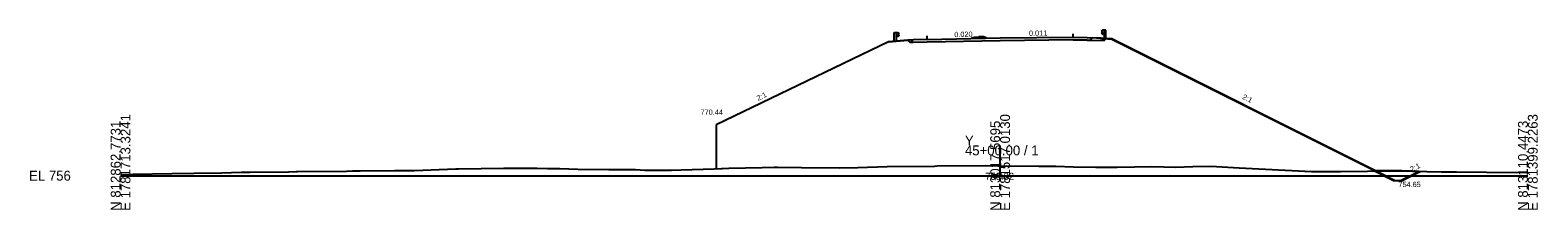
# Model space of a CAD drawing. Extents: x -12583 to 5303, y -44 to 25667.
# Drawn here: x 2874.3 to 3302.8, y 5490.3 to 5541.3 of the extents above; entities that cross this region are included whole.
import ezdxf

# ---------------------------------------------------------------- set-up
doc = ezdxf.new("R2010")
doc.units = 0
for name, color, linetype in [('Exist Cross Section Cell', 7, 'Continuous'), ('Exist XS Center Line Elevation Label', 7, 'Continuous'), ('Exist XS Ground Line', 7, 'Continuous'), ('Prop Conc 5in Monolithic Surface Mount Island', 7, 'Continuous'), ('Prop XS Ditch Standard Text', 7, 'Continuous'), ('Prop XS Dump Level', 7, 'Continuous'), ('Prop XS Earthwork Shape', 7, 'Continuous'), ('Prop XS EOT Tick Mark', 7, 'Continuous'), ('Prop XS Finish Grade', 7, 'Continuous'), ('Prop XS Finish Grade Earthwork', 7, 'Continuous'), ('Prop XS Finish Grade Paved Shoulder', 7, 'Continuous'), ('Prop XS Finish Grade Pavement', 7, 'Continuous'), ('Prop XS Guardrail', 7, 'Continuous'), ('Prop XS Pvmt Edge Slope', 7, 'Continuous'), ('Prop XS SE Text', 7, 'Continuous'), ('Prop XS Side Slope Text', 7, 'Continuous'), ('Prop XS Subgrade Earthwork', 7, 'Continuous')]:
    doc.layers.add(name, color=color, linetype=linetype)

msp = doc.modelspace()

# ---------------------------------------------------------------- linework, layer by layer
at = {"layer": 'Exist Cross Section Cell'}
for p, q in [((3150, 5500), (3150, 5508.57)), ((2900, 5500), (3150, 5500)), ((3150, 5500), (3300, 5500))]:
    msp.add_line(p, q, dxfattribs=at)
at = {"layer": 'Exist XS Ground Line'}
for p, q in [((3072.91, 5502.09), (3082.41, 5502.36)), ((3082.41, 5502.36), (3085.81, 5502.41)), ((3085.81, 5502.41), (3086.7, 5502.42)), ((3086.7, 5502.42), (3093.52, 5502.34)), ((3109.6, 5502.3), (3117.91, 5502.61)), ((3117.91, 5502.61), (3131.31, 5502.73)), ((3131.31, 5502.73), (3132.13, 5502.76)), ((3132.13, 5502.76), (3145.93, 5502.86)), ((3145.93, 5502.86), (3149.35, 5502.83)), ((3149.35, 5502.83), (3150, 5502.82)), ((3150, 5502.82), (3161.05, 5502.71)), ((3161.05, 5502.71), (3165.82, 5502.67)), ((3165.82, 5502.67), (3170.83, 5502.48)), ((3170.83, 5502.48), (3177.24, 5502.39)), ((3177.24, 5502.39), (3183.26, 5502.37)), ((3183.26, 5502.37), (3193.16, 5502.6)), ((3193.16, 5502.6), (3199.99, 5502.41)), ((3199.99, 5502.41), (3204.77, 5502.63)), ((3204.77, 5502.63), (3209.89, 5502.73)), ((3209.89, 5502.73), (3217.99, 5502.25)), ((2900, 5500.38), (2903.49, 5500.41)), ((2903.49, 5500.41), (2914.56, 5500.59)), ((2914.56, 5500.59), (2920.88, 5500.7)), ((2920.88, 5500.7), (2928.76, 5500.83)), ((2928.76, 5500.83), (2934.26, 5500.97)), ((2934.26, 5500.97), (2936.86, 5501.01)), ((2936.86, 5501.01), (2947.74, 5501.13)), ((2947.74, 5501.13), (2949.9, 5501.14)), ((2949.9, 5501.14), (2950.3, 5501.14)), ((2950.3, 5501.14), (2964.19, 5501.3)), ((2964.19, 5501.3), (2965.9, 5501.33)), ((2965.9, 5501.33), (2968.08, 5501.36)), ((2968.08, 5501.36), (2977.84, 5501.51)), ((2977.84, 5501.51), (2983.51, 5501.51)), ((2983.51, 5501.51), (2995.34, 5501.93)), ((2995.34, 5501.93), (2996.06, 5501.94)), ((2996.06, 5501.94), (3008.9, 5502.17)), ((3008.9, 5502.17), (3018.45, 5502.09)), ((3018.45, 5502.09), (3021.36, 5502.06)), ((3021.36, 5502.06), (3024.82, 5502)), ((3024.82, 5502), (3030.01, 5501.84)), ((3030.01, 5501.84), (3038.78, 5501.73)), ((3038.78, 5501.73), (3046.36, 5501.71)), ((3046.36, 5501.71), (3049.04, 5501.59)), ((3049.04, 5501.59), (3052.99, 5501.53)), ((3052.99, 5501.53), (3055.39, 5501.54)), ((3055.39, 5501.54), (3056.64, 5501.53)), ((3056.64, 5501.53), (3059.38, 5501.62)), ((3059.38, 5501.62), (3068.7, 5501.92)), ((3068.7, 5501.92), (3072.91, 5502.09)), ((3093.52, 5502.34), (3104.39, 5502.26)), ((3104.39, 5502.26), (3109.6, 5502.3)), ((3217.99, 5502.25), (3238.49, 5501.23)), ((3238.49, 5501.23), (3246.77, 5501.14)), ((3246.77, 5501.14), (3254.38, 5501.31)), ((3254.38, 5501.31), (3264.19, 5501.39)), ((3264.19, 5501.39), (3267.22, 5501.28)), ((3267.22, 5501.28), (3275.36, 5501.06)), ((3275.36, 5501.06), (3279.73, 5501.05)), ((3279.73, 5501.05), (3296.73, 5500.88)), ((3296.73, 5500.88), (3300, 5501))]:
    msp.add_line(p, q, dxfattribs=at)
at = {"layer": 'Prop Conc 5in Monolithic Surface Mount Island'}
for p, q in [((3142, 5539.1), (3142.74, 5539.36)), ((3142, 5538.93), (3142, 5539.1)), ((3142.74, 5539.36), (3143.99, 5539.41)), ((3145.24, 5539.41), (3143.99, 5539.41)), ((3146, 5539.18), (3145.24, 5539.41)), ((3146, 5539.01), (3146, 5539.18))]:
    msp.add_line(p, q, dxfattribs=at)
at = {"layer": 'Prop XS Dump Level'}
for p, q in [((3129.25, 5538.67), (3150, 5539.09)), ((3150, 5539.09), (3170.75, 5539.31))]:
    msp.add_line(p, q, dxfattribs=at)
at = {"layer": 'Prop XS Earthwork Shape'}
for points in [[(3069.3, 5514.44), (3069.3, 5501.94), (3072.91, 5502.09), (3082.41, 5502.36), (3085.81, 5502.41), (3086.7, 5502.42), (3093.52, 5502.34), (3104.39, 5502.26), (3109.6, 5502.3), (3117.91, 5502.61), (3131.31, 5502.73), (3132.13, 5502.76), (3145.93, 5502.86), (3149.35, 5502.83), (3150, 5502.82), (3161.05, 5502.71), (3165.82, 5502.67), (3170.83, 5502.48), (3177.24, 5502.39), (3183.26, 5502.37), (3193.16, 5502.6), (3199.99, 5502.41), (3204.77, 5502.63), (3209.89, 5502.73), (3217.99, 5502.25), (3238.49, 5501.23), (3246.77, 5501.14), (3254.38, 5501.31), (3256.44, 5501.33), (3181.75, 5538.67), (3176.25, 5539.11), (3175.56, 5538.42), (3174.75, 5538.44), (3170.75, 5538.52), (3150, 5538.3), (3129.25, 5537.88), (3125.25, 5537.8), (3124.44, 5537.79), (3123.75, 5538.47), (3118.25, 5538.03)], [(3263.8, 5498.65), (3268.97, 5501.23), (3267.22, 5501.28), (3264.19, 5501.39), (3256.44, 5501.33), (3261.8, 5498.65)]]:
    msp.add_lwpolyline(points, close=True, dxfattribs=at)
at = {"layer": 'Prop XS EOT Tick Mark'}
for p, q in [((3129.25, 5538.67), (3129.25, 5539.67)), ((3170.75, 5539.31), (3170.75, 5540.31))]:
    msp.add_line(p, q, dxfattribs=at)
at = {"layer": 'Prop XS Finish Grade'}
for p, q in [((3125.25, 5538.59), (3123.75, 5538.47)), ((3178.75, 5539.15), (3180.25, 5539.03))]:
    msp.add_line(p, q, dxfattribs=at)
at = {"layer": 'Prop XS Finish Grade Earthwork'}
for p, q in [((3118.25, 5538.03), (3069.3, 5514.44)), ((3118.25, 5538.03), (3123.75, 5538.47)), ((3180.25, 5539.03), (3181.75, 5538.91)), ((3181.75, 5538.91), (3256.91, 5501.33)), ((3069.3, 5514.44), (3069.3, 5501.94)), ((3256.91, 5501.33), (3262.28, 5498.65)), ((3262.28, 5498.65), (3264.28, 5498.65)), ((3264.28, 5498.65), (3269.43, 5501.22))]:
    msp.add_line(p, q, dxfattribs=at)
at = {"layer": 'Prop XS Finish Grade Paved Shoulder'}
for p, q in [((3129.25, 5538.67), (3125.25, 5538.59)), ((3170.75, 5539.31), (3178.75, 5539.15))]:
    msp.add_line(p, q, dxfattribs=at)
at = {"layer": 'Prop XS Finish Grade Pavement'}
for p, q in [((3129.25, 5538.67), (3150, 5539.09)), ((3150, 5539.09), (3170.75, 5539.31)), ((3150, 5539.09), (3170.75, 5539.31))]:
    msp.add_line(p, q, dxfattribs=at)
at = {"layer": 'Prop XS Guardrail'}
for p, q in [((3178.78, 5541.11), (3178.75, 5541.05)), ((3178.75, 5541.05), (3178.78, 5540.99)), ((3179.07, 5541.31), (3178.78, 5541.11)), ((3178.78, 5540.99), (3179.07, 5540.79)), ((3179.57, 5541.31), (3179.07, 5541.31)), ((3180.07, 5541.31), (3179.57, 5541.31)), ((3179.57, 5541.31), (3179.57, 5538.81)), ((3180.07, 5538.81), (3180.07, 5541.31)), ((3119.93, 5540.67), (3120.43, 5540.67)), ((3119.93, 5538.17), (3119.93, 5540.67)), ((3120.43, 5540.67), (3120.93, 5540.67)), ((3120.43, 5540.67), (3120.43, 5538.17)), ((3120.93, 5539.54), (3120.43, 5539.54)), ((3120.93, 5540.67), (3121.22, 5540.47)), ((3121.22, 5540.35), (3120.93, 5540.15)), ((3120.93, 5540.15), (3120.93, 5540.06)), ((3120.93, 5540.06), (3121.22, 5539.86)), ((3121.22, 5539.74), (3120.93, 5539.54)), ((3121.22, 5540.47), (3121.25, 5540.41)), ((3121.25, 5540.41), (3121.22, 5540.35)), ((3121.22, 5539.86), (3121.25, 5539.8)), ((3121.25, 5539.8), (3121.22, 5539.74)), ((3178.78, 5540.49), (3178.75, 5540.43)), ((3178.75, 5540.43), (3178.78, 5540.37)), ((3179.07, 5540.69), (3178.78, 5540.49)), ((3178.78, 5540.37), (3179.07, 5540.17)), ((3179.07, 5540.79), (3179.07, 5540.69)), ((3179.07, 5540.17), (3179.57, 5540.17))]:
    msp.add_line(p, q, dxfattribs=at)
at = {"layer": 'Prop XS Pvmt Edge Slope'}
for p, q in [((3125.25, 5538.59), (3124.44, 5537.79)), ((3178.75, 5539.15), (3179.56, 5538.34))]:
    msp.add_line(p, q, dxfattribs=at)
at = {"layer": 'Prop XS Subgrade Earthwork'}
for p, q in [((3124.44, 5537.79), (3123.75, 5538.47)), ((3125.25, 5537.8), (3124.44, 5537.79)), ((3129.25, 5537.88), (3125.25, 5537.8)), ((3150, 5538.3), (3129.25, 5537.88)), ((3170.75, 5538.52), (3150, 5538.3)), ((3170.75, 5538.52), (3174.75, 5538.44)), ((3174.75, 5538.44), (3179.56, 5538.34)), ((3179.56, 5538.34), (3180.25, 5539.03))]:
    msp.add_line(p, q, dxfattribs=at)

# ---------------------------------------------------------------- texts
at = {"layer": 'Exist Cross Section Cell'}
for s, p in [('N 812862.7731', (2900, 5490)), ('E 1781713.3241', (2902.8, 5490)), ('N 813017.5695', (3150, 5490)), ('E 1781517.0130', (3152.8, 5490)), ('N 813110.4473', (3300, 5490)), ('E 1781399.2263', (3302.8, 5490))]:
    msp.add_text(s, height=2.8, rotation=90, dxfattribs=at).set_placement(p)
for s, p in [('Y', (3140, 5508.57)), ('45+00.00 / 1', (3140, 5505.77)), ('EL 756', (2874, 5498.6))]:
    msp.add_text(s, height=2.8, dxfattribs=at).set_placement(p)
at = {"layer": 'Exist XS Center Line Elevation Label'}
msp.add_text('758.82', height=2, dxfattribs=at).set_placement((3145.79, 5498.82))
at = {"layer": 'Prop XS Ditch Standard Text'}
for s, p in [('770.44', (3064.87, 5517.28)), ('754.65', (3263.22, 5496.77))]:
    msp.add_text(s, height=1.5, dxfattribs=at).set_placement(p)
at = {"layer": 'Prop XS Dump Level'}
for p in [(3121.25, 5538.23), (3178.75, 5538.87)]:
    msp.add_text('Case2', height=0.04, dxfattribs=at).set_placement(p)
at = {"layer": 'Prop XS SE Text'}
for s, rotation, p in [('0.020', 1.1458, (3137, 5539.33)), ('0.011', 0.6127, (3158.21, 5539.68)), ('0.011', 0.6127, (3158.21, 5539.68))]:
    msp.add_text(s, height=1.5, rotation=rotation, dxfattribs=at).set_placement(p)
at = {"layer": 'Prop XS Side Slope Text'}
for rotation, p in [(26.5651, (3081.26, 5521.22)), (333.4349, (3218.68, 5521.88)), (26.5651, (3267.01, 5501.06))]:
    msp.add_text('2:1', height=1.5, rotation=rotation, dxfattribs=at).set_placement(p)

doc.saveas('drawing.dxf')
